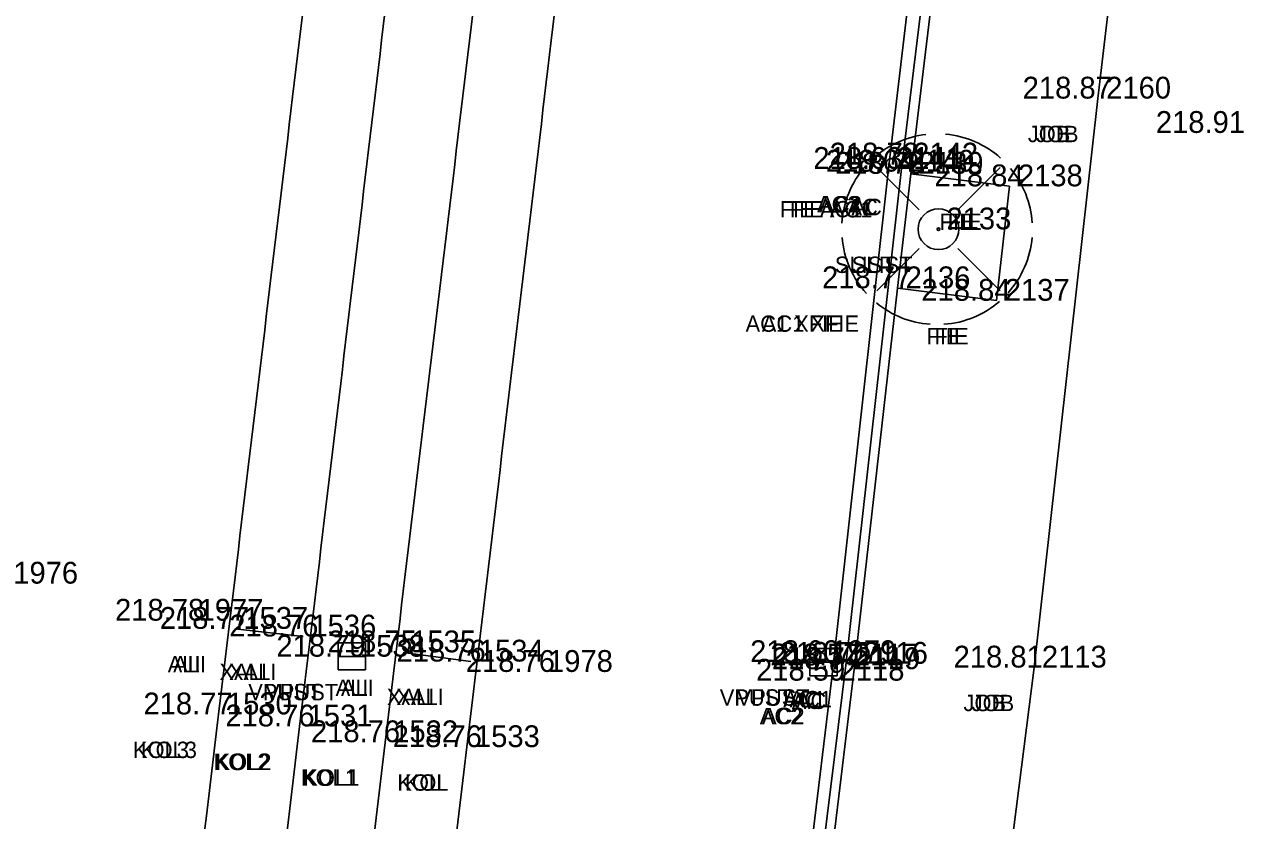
# Model space of a CAD drawing. Extents: x -471047 to -470889, y -1102859 to -1102000.
# Drawn here: x -470957.1 to -470934.71, y -1102353.46 to -1102338.85 of the extents above; entities that cross this region are included whole.
import ezdxf

# ---------------------------------------------------------------- set-up
doc = ezdxf.new("R2010")
doc.units = 0
for name, color, linetype in [('Vrstva 1', 7, 'Continuous'), ('Vrstva 16', 7, 'Continuous'), ('Vrstva 25', 7, 'Continuous'), ('Vrstva 29', 7, 'Continuous'), ('Vrstva 34', 7, 'Continuous'), ('Vrstva 35', 7, 'Continuous'), ('Vrstva 36', 7, 'Continuous'), ('Vrstva 38', 7, 'Continuous'), ('Vrstva 5', 7, 'Continuous'), ('Vrstva 7', 7, 'Continuous'), ('Vrstva 8', 7, 'Continuous')]:
    doc.layers.add(name, color=color, linetype=linetype)

msp = doc.modelspace()

# ---------------------------------------------------------------- linework, layer by layer
at = {"layer": 'Vrstva 1'}
for points in [[(-471040.344, -1102858.385), (-471031.676, -1102846.187), (-471026.357, -1102838.629), (-471023.212, -1102833.975), (-471019.21, -1102827.465), (-471016.861, -1102823.272), (-471013.099, -1102815.912), (-471010.824, -1102810.955), (-471007.329, -1102802.292), (-471005.34, -1102796.515), (-471002.842, -1102787.838), (-471001.3, -1102780.997), (-471000.19, -1102774.713), (-470999.247, -1102768.204), (-470998.794, -1102764.784), (-470997.199, -1102751.812), (-470994.899, -1102732.807), (-470992.551, -1102713.262), (-470990.326, -1102694.887), (-470988.122, -1102676.57), (-470985.812, -1102657.305), (-470983.537, -1102638.407), (-470981.386, -1102620.622), (-470979.843, -1102608.014), (-470976.377, -1102579.253), (-470972.945, -1102550.69), (-470970.475, -1102530.206), (-470967.905, -1102508.801), (-470965.053, -1102485.131), (-470962.734, -1102465.9), (-470960.173, -1102444.812), (-470957.795, -1102425.103), (-470954.965, -1102401.839), (-470953.834, -1102392.574), (-470952.33, -1102379.985), (-470950.744, -1102366.853), (-470948.978, -1102352.106), (-470947.037, -1102335.844), (-470944.949, -1102318.462), (-470944.013, -1102310.745), (-470942.39, -1102297.267), (-470939.519, -1102273.45), (-470937.593, -1102257.43), (-470936.064, -1102244.81), (-470934.114, -1102228.634), (-470931.621, -1102207.856), (-470929.536, -1102190.857), (-470926.572, -1102166.31), (-470924.91, -1102152.663), (-470923.413, -1102140.333), (-470921.923, -1102127.669), (-470921.155, -1102120.084), (-470920.446, -1102109.574), (-470919.912, -1102099.137), (-470919.63, -1102088.981), (-470919.523, -1102081.193), (-470919.563, -1102070.395), (-470919.714, -1102064.236), (-470920.134, -1102054.704), (-470920.462, -1102047.615), (-470920.599, -1102044.52), (-470920.743, -1102041.873), (-470921.125, -1102034.455), (-470921.774, -1102030.337), (-470922.418, -1102027.787), (-470923.734, -1102023.93), (-470924.872, -1102021.434), (-470926.752, -1102018.182), (-470927.953, -1102016.45), (-470929.616, -1102014.424), (-470932.252, -1102011.756), (-470935.111, -1102009.425), (-470938.391, -1102007.371), (-470942.651, -1102005.401)], [(-471041.328, -1102857.18), (-471032.144, -1102844.242), (-471027.583, -1102837.763), (-471024.388, -1102833.028), (-471020.451, -1102826.6), (-471018.089, -1102822.378), (-471014.542, -1102815.445), (-471012.233, -1102810.418), (-471009.247, -1102803.108), (-471006.795, -1102796.098), (-471004.315, -1102787.532), (-471002.782, -1102780.723), (-471001.674, -1102774.458), (-471000.75, -1102768.095), (-471000.28, -1102764.601), (-470998.692, -1102751.741), (-470996.378, -1102732.635), (-470994.028, -1102713.058), (-470991.808, -1102694.749), (-470989.616, -1102676.447), (-470987.284, -1102657.013), (-470985.031, -1102638.272), (-470982.87, -1102620.431), (-470981.334, -1102607.933), (-470977.881, -1102579.263), (-470974.429, -1102550.492), (-470971.964, -1102530.054), (-470969.391, -1102508.607), (-470966.54, -1102484.984), (-470964.231, -1102465.853), (-470961.679, -1102444.752), (-470959.304, -1102425.078), (-470956.455, -1102401.634), (-470955.339, -1102392.489), (-470953.812, -1102379.71), (-470952.249, -1102366.808), (-470950.479, -1102352.023), (-470948.536, -1102335.868), (-470946.426, -1102318.233), (-470945.493, -1102310.531), (-470943.864, -1102297.013), (-470940.984, -1102273.071), (-470939.078, -1102257.195), (-470937.559, -1102244.684), (-470935.592, -1102228.353), (-470933.101, -1102207.653), (-470931.011, -1102190.57), (-470928.046, -1102166.021), (-470926.409, -1102152.578), (-470924.898, -1102140.121), (-470923.427, -1102127.544), (-470922.647, -1102119.826), (-470921.919, -1102109.229), (-470921.42, -1102099.134), (-470921.127, -1102089.016), (-470921.023, -1102081.453), (-470921.061, -1102070.468), (-470921.209, -1102064.314), (-470921.666, -1102053.966), (-470922.156, -1102043.345), (-470922.299, -1102039.934), (-470922.637, -1102034.36), (-470923.091, -1102031.241), (-470923.847, -1102028.247), (-470925.083, -1102024.594), (-470926.222, -1102022.086), (-470928.04, -1102018.943), (-470929.138, -1102017.357), (-470930.929, -1102015.175), (-470933.062, -1102013.049), (-470936.379, -1102010.368), (-470939.169, -1102008.662), (-470942.899, -1102006.906), (-470945.661, -1102005.908)], [(-471043.557, -1102855.955), (-471035.129, -1102844.026), (-471029.872, -1102836.499), (-471026.577, -1102831.578), (-471022.675, -1102825.415), (-471020.123, -1102821.053), (-471016.667, -1102814.59), (-471014.208, -1102809.45), (-471011.177, -1102802.451), (-471008.55, -1102795.333), (-471006.082, -1102787.209), (-471004.464, -1102780.376), (-471003.265, -1102774.167), (-471002.327, -1102767.948), (-471001.636, -1102762.527), (-471000.297, -1102751.605), (-470997.959, -1102732.524), (-470995.602, -1102712.802), (-470993.412, -1102694.623), (-470991.21, -1102676.17), (-470988.891, -1102656.857), (-470986.625, -1102638.083), (-470984.455, -1102620.195), (-470982.936, -1102607.733), (-470979.497, -1102579.223), (-470976.023, -1102550.279), (-470973.554, -1102529.822), (-470970.991, -1102508.497), (-470968.146, -1102484.787), (-470965.835, -1102465.72), (-470963.284, -1102444.529), (-470960.91, -1102424.942), (-470958.043, -1102401.343), (-470956.946, -1102392.356), (-470955.396, -1102379.408), (-470953.851, -1102366.636), (-470952.049, -1102351.733), (-470950.124, -1102335.611), (-470948.034, -1102318.083), (-470947.094, -1102310.328), (-470945.421, -1102296.51), (-470942.58, -1102272.848), (-470940.675, -1102256.948), (-470939.176, -1102244.526), (-470937.187, -1102228.174), (-470934.708, -1102207.467), (-470932.621, -1102190.433), (-470929.634, -1102165.778), (-470928.004, -1102152.415), (-470926.45, -1102139.595), (-470925.003, -1102127.418), (-470924.249, -1102119.695), (-470923.515, -1102109.093), (-470923.018, -1102099.069), (-470922.711, -1102088.911), (-470922.643, -1102081.356), (-470922.797, -1102070.414), (-470923.018, -1102064.454), (-470923.52, -1102053.203), (-470923.823, -1102047.529), (-470924.123, -1102041.506), (-470924.462, -1102037.486), (-470924.934, -1102031.904), (-470925.664, -1102028.672), (-470926.771, -1102025.506), (-470927.959, -1102022.914), (-470929.674, -1102020.028), (-470930.76, -1102018.498), (-470932.447, -1102016.478), (-470935.215, -1102013.816), (-470937.644, -1102011.98), (-470940.381, -1102010.371), (-470943.968, -1102008.669), (-470947.145, -1102007.524), (-470950.874, -1102006.74)], [(-471044.756, -1102855.056), (-471036.376, -1102843.177), (-471031.167, -1102835.741), (-471027.859, -1102830.8), (-471023.934, -1102824.593), (-471021.43, -1102820.312), (-471018.011, -1102813.91), (-471015.536, -1102808.75), (-471012.578, -1102801.897), (-471009.95, -1102794.77), (-471007.561, -1102786.914), (-471005.936, -1102780.074), (-471004.727, -1102773.818), (-471003.828, -1102767.827), (-471003.121, -1102762.345), (-471001.787, -1102751.467), (-470999.446, -1102732.348), (-470997.073, -1102712.539), (-470994.902, -1102694.521), (-470992.696, -1102676.023), (-470990.376, -1102656.68), (-470988.131, -1102638.071), (-470985.947, -1102620.018), (-470984.417, -1102607.512), (-470980.993, -1102579.08), (-470977.514, -1102550.137), (-470975.048, -1102529.649), (-470972.488, -1102508.37), (-470969.618, -1102484.508), (-470967.34, -1102465.669), (-470964.767, -1102444.39), (-470962.402, -1102424.781), (-470959.534, -1102401.193), (-470958.432, -1102392.151), (-470956.883, -1102379.208), (-470955.335, -1102366.424), (-470953.535, -1102351.506), (-470951.606, -1102335.399), (-470949.519, -1102317.94), (-470948.575, -1102310.159), (-470946.889, -1102296.144), (-470944.056, -1102272.618), (-470942.139, -1102256.659), (-470940.657, -1102244.341), (-470938.638, -1102227.749), (-470936.19, -1102207.298), (-470934.102, -1102190.255), (-470931.124, -1102165.639), (-470929.492, -1102152.254), (-470927.915, -1102139.252), (-470926.46, -1102127.103), (-470925.74, -1102119.604), (-470925.012, -1102108.913), (-470924.523, -1102099.054), (-470924.217, -1102088.866), (-470924.148, -1102081.334), (-470924.301, -1102070.391), (-470924.518, -1102064.43), (-470924.97, -1102054.435), (-470925.588, -1102041.569), (-470925.963, -1102035.313), (-470926.405, -1102032.225), (-470927.078, -1102029.198), (-470928.123, -1102026.148), (-470929.318, -1102023.558), (-470930.84, -1102020.97), (-470931.868, -1102019.515), (-470933.443, -1102017.605), (-470936.26, -1102014.885), (-470938.429, -1102013.255), (-470941.213, -1102011.639), (-470944.847, -1102009.927), (-470947.723, -1102008.912), (-470951.444, -1102008.161), (-470954.511, -1102007.931), (-470957.895, -1102008.041)]]:
    msp.add_spline(points, degree=3, dxfattribs=at)
at = {"layer": 'Vrstva 16'}
for p, q in [((-470940.684, -1102342.252), (-470941.458, -1102341.477)), ((-470939.974, -1102342.252), (-470939.198, -1102341.477)), ((-470940.684, -1102342.962), (-470941.458, -1102343.737)), ((-470939.974, -1102342.962), (-470939.198, -1102343.737))]:
    msp.add_line(p, q, dxfattribs=at)
for radius in [0.375, 0.025, 0.025]:
    msp.add_circle((-470940.328, -1102342.607), radius, dxfattribs=at)
for start, end in [(96.7144, 130.447), (48.1897, 84.9117), (139.23, 176.4602), (3.8615, 39.6013), (184.9408, 222.2827), (318.1086, 355.0481), (230.4703, 265.8356), (274.1732, 310.7861)]:
    msp.add_arc((-470940.354, -1102342.607), 1.75, start, end, dxfattribs=at)
at = {"layer": 'Vrstva 25'}
for p, q in [((-470951.34, -1102350.195), (-470951.34, -1102350.695)), ((-470950.84, -1102350.195), (-470951.34, -1102350.195)), ((-470950.84, -1102350.695), (-470950.84, -1102350.195)), ((-470942.687, -1102350.301), (-470942.687, -1102350.801)), ((-470942.187, -1102350.301), (-470942.687, -1102350.301)), ((-470942.187, -1102350.801), (-470942.187, -1102350.301)), ((-470951.34, -1102350.445), (-470950.84, -1102350.445)), ((-470951.34, -1102350.695), (-470950.84, -1102350.695)), ((-470942.687, -1102350.551), (-470942.187, -1102350.551)), ((-470942.687, -1102350.801), (-470942.187, -1102350.801))]:
    msp.add_line(p, q, dxfattribs=at)
at = {"layer": 'Vrstva 29'}
for p, q in [((-470951.984, -1102350.079), (-470953.234, -1102349.941)), ((-470948.91, -1102350.539), (-470950.148, -1102350.374))]:
    msp.add_line(p, q, dxfattribs=at)
at = {"layer": 'Vrstva 34'}
for p, q in [((-470937.4, -1102340.21), (-470937.4, -1102340.21)), ((-470934.87, -1102340.84), (-470934.87, -1102340.84)), ((-470941.24, -1102341.5), (-470941.24, -1102341.5)), ((-470941.01, -1102341.55), (-470941.01, -1102341.55)), ((-470940.94, -1102341.42), (-470940.94, -1102341.42)), ((-470940.84, -1102341.59), (-470940.84, -1102341.59)), ((-470939.02, -1102341.82), (-470939.02, -1102341.82)), ((-470940.33, -1102342.61), (-470940.33, -1102342.61)), ((-470941.08, -1102343.69), (-470941.08, -1102343.69)), ((-470939.26, -1102343.92), (-470939.26, -1102343.92)), ((-470954.05, -1102349.79), (-470954.05, -1102349.79)), ((-470953.23, -1102349.94), (-470953.23, -1102349.94)), ((-470951.98, -1102350.08), (-470951.98, -1102350.08)), ((-470951.09, -1102350.45), (-470951.09, -1102350.45)), ((-470950.15, -1102350.37), (-470950.15, -1102350.37)), ((-470948.91, -1102350.54), (-470948.91, -1102350.54)), ((-470947.64, -1102350.73), (-470947.64, -1102350.73)), ((-470942.44, -1102350.55), (-470942.44, -1102350.55)), ((-470942.03, -1102350.61), (-470942.03, -1102350.61)), ((-470942, -1102350.68), (-470942, -1102350.68)), ((-470941.86, -1102350.58), (-470941.86, -1102350.58)), ((-470938.58, -1102350.65), (-470938.58, -1102350.65)), ((-470942.29, -1102350.89), (-470942.29, -1102350.89)), ((-470953.53, -1102351.51), (-470953.53, -1102351.51)), ((-470952.05, -1102351.73), (-470952.05, -1102351.73)), ((-470950.48, -1102352.02), (-470950.48, -1102352.02)), ((-470948.98, -1102352.11), (-470948.98, -1102352.11))]:
    msp.add_line(p, q, dxfattribs=at)
at = {"layer": 'Vrstva 5'}
for p, q in [((-470941.243, -1102341.499), (-470940.783, -1102337.577)), ((-470942.292, -1102350.885), (-470941.243, -1102341.499)), ((-470943.326, -1102359.422), (-470942.292, -1102350.885))]:
    msp.add_line(p, q, dxfattribs=at)
at = {"layer": 'Vrstva 7'}
for p, q in [((-470940.838, -1102341.592), (-470940.332, -1102337.406)), ((-470941.082, -1102343.686), (-470940.838, -1102341.592)), ((-470941.862, -1102350.584), (-470941.082, -1102343.686)), ((-470942.943, -1102359.455), (-470941.862, -1102350.584))]:
    msp.add_line(p, q, dxfattribs=at)
at = {"layer": 'Vrstva 8'}
for p, q in [((-470937.403, -1102340.207), (-470935.278, -1102322.312)), ((-470941.01, -1102341.55), (-470940.528, -1102337.565)), ((-470938.575, -1102350.647), (-470937.403, -1102340.207)), ((-470942.029, -1102350.606), (-470941.01, -1102341.55)), ((-470939.024, -1102341.82), (-470940.838, -1102341.592)), ((-470939.262, -1102343.917), (-470939.024, -1102341.82)), ((-470941.082, -1102343.686), (-470939.262, -1102343.917)), ((-470943.117, -1102359.392), (-470942.029, -1102350.606)), ((-470940.01, -1102362.086), (-470938.575, -1102350.647))]:
    msp.add_line(p, q, dxfattribs=at)

# ---------------------------------------------------------------- texts
at = {"layer": 'Vrstva 35'}
for s, p in [('JOB', (-470938.689, -1102341.01)), ('JOB', (-470938.539, -1102341.01)), ('AC2', (-470942.556, -1102342.3)), ('AC2', (-470942.515, -1102342.3)), ('FIE AC1', (-470943.24, -1102342.39)), ('FIE AC1', (-470943.057, -1102342.39)), ('AC', (-470941.999, -1102342.35)), ('AC', (-470941.924, -1102342.35)), ('FIE', (-470940.307, -1102342.62)), ('FIE', (-470940.159, -1102342.62)), ('SLIST', (-470942.23, -1102343.41)), ('SLIST', (-470941.919, -1102343.41)), ('AC1 XFIE', (-470943.867, -1102344.49)), ('AC1 XFIE', (-470943.569, -1102344.49)), ('FIE', (-470940.547, -1102344.72)), ('FIE', (-470940.399, -1102344.72)), ('ALI', (-470954.468, -1102350.74)), ('ALI', (-470954.369, -1102350.74)), ('XALI', (-470953.518, -1102350.88)), ('XALI', (-470953.344, -1102350.88)), ('VPUST', (-470952.99, -1102351.25)), ('VPUST', (-470952.679, -1102351.25)), ('ALI', (-470951.388, -1102351.17)), ('ALI', (-470951.289, -1102351.17)), ('XALI', (-470950.448, -1102351.34)), ('XALI', (-470950.274, -1102351.34)), ('VPUST', (-470944.34, -1102351.35)), ('VPUST', (-470944.029, -1102351.35)), ('AC1', (-470943.177, -1102351.38)), ('AC1', (-470943.06, -1102351.38)), ('AC', (-470943.019, -1102351.41)), ('AC', (-470942.944, -1102351.41)), ('JOB', (-470939.869, -1102351.45)), ('JOB', (-470939.719, -1102351.45)), ('AC2', (-470943.606, -1102351.69)), ('AC2', (-470943.565, -1102351.69)), ('KOL3', (-470955.105, -1102352.31)), ('KOL3', (-470954.958, -1102352.31)), ('KOL2', (-470953.625, -1102352.53)), ('KOL2', (-470953.591, -1102352.53)), ('KOL1', (-470952.022, -1102352.82)), ('KOL1', (-470951.98, -1102352.82)), ('KOL', (-470950.255, -1102352.91)), ('KOL', (-470950.119, -1102352.91))]:
    msp.add_text(s, height=0.3, dxfattribs=at).set_placement(p)
at = {"layer": 'Vrstva 36'}
for s, p in [(' 2160', (-470937.4, -1102340.21)), (' 2141', (-470941.24, -1102341.5)), (' 2142', (-470940.94, -1102341.42)), (' 2140', (-470941.01, -1102341.55)), (' 2139', (-470940.84, -1102341.59)), (' 2138', (-470939.02, -1102341.82)), (' 2133', (-470940.33, -1102342.61)), (' 2136', (-470941.08, -1102343.69)), (' 2137', (-470939.26, -1102343.92)), (' 1976', (-470957.45, -1102349.11)), (' 1977', (-470954.05, -1102349.79)), (' 1537', (-470953.23, -1102349.94)), (' 1536', (-470951.98, -1102350.08)), (' 1538', (-470951.09, -1102350.45)), (' 1535', (-470950.15, -1102350.37)), (' 1534', (-470948.91, -1102350.54)), (' 1979', (-470942.44, -1102350.55)), (' 2117', (-470942.03, -1102350.61)), (' 2119', (-470942, -1102350.68)), (' 2116', (-470941.86, -1102350.58)), (' 2113', (-470938.58, -1102350.65)), (' 1978', (-470947.64, -1102350.73)), (' 2118', (-470942.29, -1102350.89)), (' 1530', (-470953.53, -1102351.51)), (' 1531', (-470952.05, -1102351.73)), (' 1532', (-470950.48, -1102352.02)), (' 1533', (-470948.98, -1102352.11))]:
    msp.add_text(s, height=0.4, dxfattribs=at).set_placement(p)
at = {"layer": 'Vrstva 38'}
for s, p in [('218.87 ', (-470938.783, -1102340.21)), ('218.91 ', (-470936.34, -1102340.84)), ('218.63 ', (-470942.623, -1102341.5)), ('218.78 ', (-470942.324, -1102341.42)), ('218.64 ', (-470942.392, -1102341.55)), ('218.78 ', (-470942.224, -1102341.59)), ('218.84 ', (-470940.402, -1102341.82)), ('218.77 ', (-470942.463, -1102343.69)), ('218.84 ', (-470940.642, -1102343.92)), ('218.78 ', (-470955.434, -1102349.79)), ('218.77 ', (-470954.613, -1102349.94)), ('218.76 ', (-470953.34, -1102350.08)), ('218.79 ', (-470952.474, -1102350.45)), ('218.75 ', (-470951.534, -1102350.37)), ('218.76 ', (-470950.27, -1102350.54)), ('218.60 ', (-470943.783, -1102350.55)), ('218.57 ', (-470943.413, -1102350.61)), ('218.74 ', (-470943.382, -1102350.68)), ('218.75 ', (-470943.244, -1102350.58)), ('218.81 ', (-470940.05, -1102350.65)), ('218.76 ', (-470949, -1102350.73)), ('218.59 ', (-470943.674, -1102350.89)), ('218.77 ', (-470954.913, -1102351.51)), ('218.76 ', (-470953.41, -1102351.73)), ('218.76 ', (-470951.84, -1102352.02)), ('218.76 ', (-470950.34, -1102352.11))]:
    msp.add_text(s, height=0.4, dxfattribs=at).set_placement(p)

doc.saveas('drawing.dxf')
